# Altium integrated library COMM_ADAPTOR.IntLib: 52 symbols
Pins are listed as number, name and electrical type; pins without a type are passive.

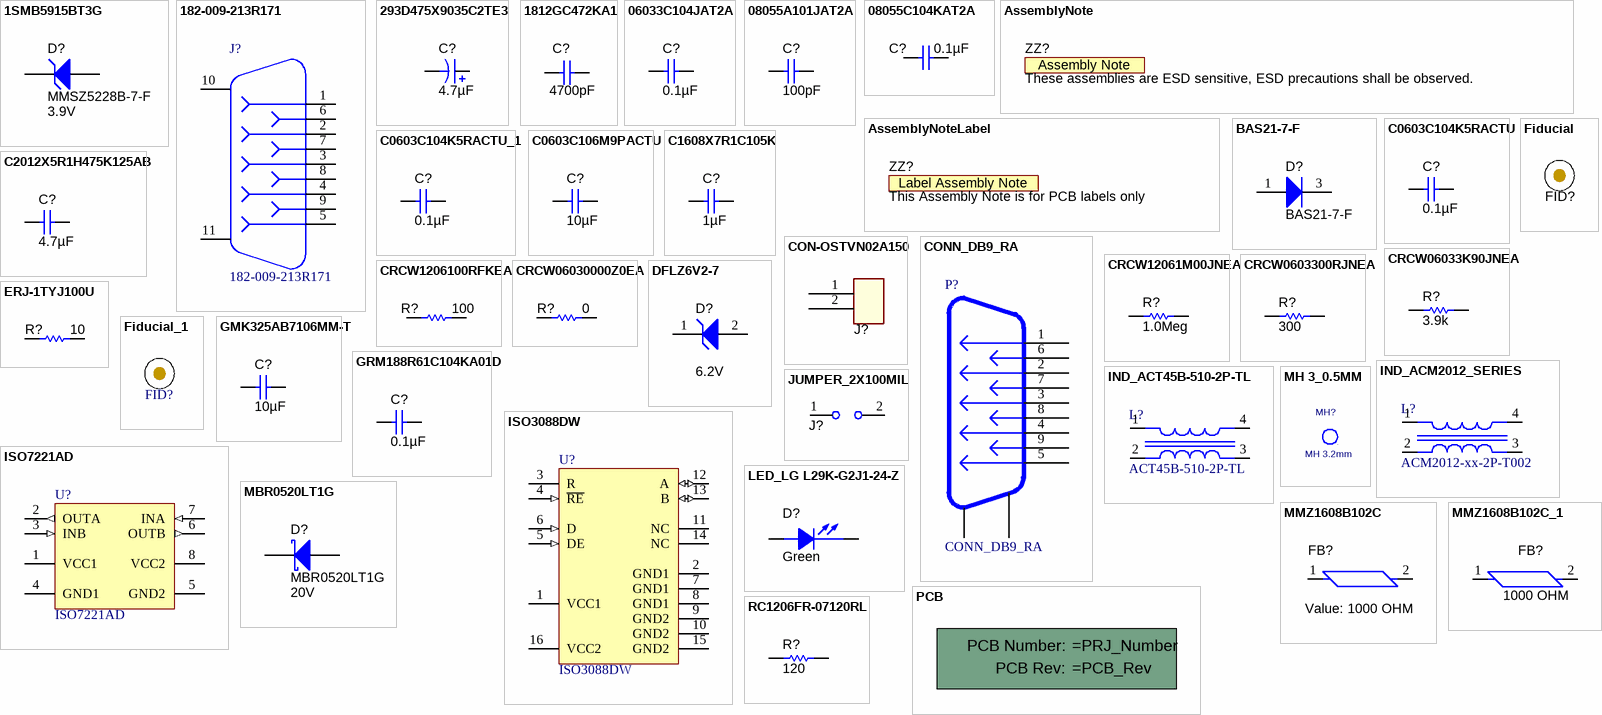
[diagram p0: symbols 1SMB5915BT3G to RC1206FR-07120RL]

## 1SMB5915BT3G
designator D?, comment MMSZ5228B-7-F  value 3.9V
DIODE ZENER 3.9V 500MW SOD123; Manufacturer: Diodes Incorporated; U/M: EA; Power_W: 0.55; Vz_V: 3.9; Value1: 0.55W; RJA_CperW: 226
signal-integrity model Diode
footprint sod-123 (On Semi recommended land pattern)
pins: 1 K, 2 A

## 182-009-213R171
designator J?
CONN DB9 FEMALE R/A SOLDER TH; Manufacturer: NorComp; SymbolCreator: a0412235; CompType: Connector; U/M: EA
footprint NORCOMP_182-009-213R171
pins: 1, 2, 3, 4, 5, 6, 7, 8, 9, 10, 11

## 293D475X9035C2TE3
designator C?  ValueDisplayed: 4.7µF  (hidden comment: 293D475X9035C2TE3)
CAP, TA, 4.7uF, 35V, +/-10%, 1.9 ohm, SMD; Manufacturer: Vishay-Sprague; Polarized: Y; CompType: Capacitor; U/M: EA; Cap_F: 0.0000047; Tolerance_%: 10; Value1: 1.9 ohm; VDC_V: 35; ESR_Ohm: 1.9; IRMS_A: 0.24; TaMin_C: -55; TaMax_C: 125; Cap_Case: C
signal-integrity model Cap
simulation model Cap
footprint 6032-28 (Medium Density IPC based on Vishay Sprague 293D datasheet.)
pins: 1 +, 2 -

## 1812GC472KA1
designator C?  ValueDisplayed: 4700pF  (hidden comment: 1812GC472KA1)
CAP, CERM, 4700pF, 2000V, +/-10%, X7R, 1812; Manufacturer: AVX; Polarized: N; CompType: Capacitor; U/M: EA; Cap_F: 0.0000000047; Tolerance_%: 10; Value1: Unknown; VDC_V: 2000; TaMin_C: -55; TaMax_C: 125; Cap_Case: 1812
signal-integrity model Cap
simulation model Cap
footprint 1812
footprint 1812M
footprint 1812L
footprint 1812_HV
pins: 1, 2

## 06033C104JAT2A
designator C?  ValueDisplayed: 0.1µF  (hidden comment: 06033C104JAT2A)
CAP, CERM, 0.1uF, 25V, +/-5%, X7R, 0603; Manufacturer: AVX; Polarized: N; CompType: Capacitor; U/M: EA; Cap_F: 0.0000001; Tolerance_%: 5; ESR_Ohm: 0.05; Value1: 0.05 ohm; VDC_V: 25; TaMin_C: -55; TaMax_C: 125; Cap_Case: 0603
signal-integrity model Cap
simulation model Cap
footprint 0603
footprint 0603M
footprint 0603L
footprint 0603_HV
pins: 1, 2

## 08055A101JAT2A
designator C?  ValueDisplayed: 100pF  (hidden comment: 08055A101JAT2A)
CAP, CERM, 100pF, 50V, +/-5%, C0G/NP0, 0805; Manufacturer: AVX; Polarized: N; CompType: Capacitor; U/M: EA; Cap_F: 0.0000000001; Tolerance_%: 5; ESR_Ohm: 0.356; Value1: 0.356 ohm; VDC_V: 50; TaMin_C: -55; TaMax_C: 125; Cap_Case: 0805
signal-integrity model Cap
simulation model Cap
footprint 0805_HV
footprint 0805
footprint 0805M
footprint 0805L
pins: 1, 2

## 08055C104KAT2A
designator C?  ValueDisplayed: 0.1µF  (hidden comment: 08055C104KAT2A)
CAP, CERM, 0.1uF, 50V, +/-10%, X7R, 0805; Manufacturer: AVX; Polarized: N; CompType: Capacitor; U/M: EA; Cap_F: 0.0000001; Tolerance_%: 10; ESR_Ohm: 0.024; Value1: 0.024 ohm; VDC_V: 50; TaMin_C: -55; TaMax_C: 125; Cap_Case: 0805
signal-integrity model Cap
simulation model Cap
footprint 0805_HV (0805 with 30mil clearance between pads)
footprint 0805
footprint 0805M
footprint 0805L
pins: 1, 2

## AssemblyNote
designator ZZ?, comment These assemblies are ESD sensitive, ESD precautions shall be observed.  (no BOM)
SymbolCreator: codlsc; CompType: AssemblyNote
footprint AssemblyNote

## AssemblyNoteLabel
designator ZZ?, comment This Assembly Note is for PCB labels only  (no BOM)
SymbolCreator: a0412235
footprint AssemblyNoteLabel

## BAS21-7-F
designator D?
Diode, Switching, 200V, 0.2A, SOT-23; Manufacturer: Diodes Inc.; U/M: EA; Vf_V: 1.25; Value2: 1.25V; Io_A: 0.2; Vr_V: 200; TJmax_C: 150; RJC_CperW: 500
footprint SOT-23 (SOT23, 3-Leads, Body 2.9x1.3mm, Pitch 0.95mm, Lead Span 2.5mm, IPC Medium Density)
footprint SOT-23M
footprint SOT-23L
pins: 1 A, 3 K

## C0603C104K5RACTU
designator C?  ValueDisplayed: 0.1µF
CAP, CERM, 0.1uF, 50V, +/-10%, X7R, 0603; PartNumber: C0603C104K5RACTU; Manufacturer: Kemet; Polarized: N; CompType: Capacitor; U/M: EA; Cap_F: 0.0000001; Tolerance_%: 10; Value1: Unknown; VDC_V: 50; TaMin_C: -55; TaMax_C: 125; Cap_Case: 0603
signal-integrity model Cap
simulation model Cap
footprint 0603 (0603 from SM-752 data)
footprint 0603M
footprint 0603L
footprint 0603_HV
pins: 1, 2

## C0603C104K5RACTU_1
designator C?, comment ValueDisplayed: 0.1µF  (hidden comment: C0603C104K5RACTU)
CAP, CERM, 0.1uF, 50V, +/-10%, X7R, 0603; Manufacturer: Kemet; Polarized: N; CompType: Capacitor; U/M: EA; Cap_F: 0.0000001; Tolerance_%: 10; Value1: Unknown; VDC_V: 50; TaMin_C: -55; TaMax_C: 125; Cap_Case: 0603
signal-integrity model Cap
simulation model Cap
footprint 0603 (0603 from SM-752 data)
footprint 0603M
footprint 0603L
footprint 0603_HV
pins: 1, 2

## C0603C106M9PACTU
designator C?  ValueDisplayed: 10µF  (hidden comment: C0603C106M9PACTU)
CAP, CERM, 10uF, 6.3V, +/-20%, X5R, 0603; Manufacturer: Kemet; Polarized: N; CompType: Capacitor; U/M: EA; Cap_F: 0.00001; Tolerance_%: 20; ESR_Ohm: 0.004; Value1: 0.004 ohm; VDC_V: 6.3; IRMS_A: 8.9; TaMin_C: -55; TaMax_C: 85; Cap_Case: 0603
signal-integrity model Cap
simulation model Cap
footprint 0603
footprint 0603M
footprint 0603L
footprint 0603_HV
pins: 1, 2

## C1608X7R1C105K
designator C?  ValueDisplayed: 1µF  (hidden comment: C1608X7R1C105K)
CAP, CERM, 1uF, 16V, +/-10%, X7R, 0603; Manufacturer: TDK; Polarized: N; CompType: Capacitor; U/M: EA; Cap_F: 0.000001; Tolerance_%: 10; ESR_Ohm: 0.0057; Value1: 0.0057 ohm; VDC_V: 16; TaMin_C: -55; TaMax_C: 125; Cap_Case: 0603
signal-integrity model Cap
simulation model Cap
footprint 0603 (0603 from SM-752 data)
footprint 0603M
footprint 0603L
footprint 0603_HV
pins: 1, 2

## C2012X5R1H475K125AB
designator C?  ValueDisplayed: 4.7µF
CAP, CERM, 4.7uF, 50V, +/-10%, X5R, 0805; PartNumber: C2012X5R1H475K125AB; Manufacturer: TDK; Polarized: N; CompType: Capacitor; U/M: EA; Cap_F: 0.0000047; Tolerance_%: 10; Value1: Unknown; VDC_V: 50; TaMin_C: -55; TaMax_C: 85; Cap_Case: 0805
signal-integrity model Cap
simulation model Cap
footprint 0805_HV (0805 with 30mil clearance between pads)
footprint 0805
footprint 0805M
footprint 0805L
pins: 1, 2

## CON-OSTVN02A150
designator J?  (value not drawn)
CONN TERM BLOCK 2.54MM 2POS PCB; Manufacturer: On Shore Technology Inc; SymbolCreator: x0120606; CompType: Terminal Block
footprint CN2_MTB_P100_PD80_D1.1_S5.54X6.5_STACK
pins: 1, 2

## CONN_DB9_RA
designator P?
Connector, 9-pin D, Right Angle, Male; Manufacturer: AMP; PartNumber: 747250-4; area: 1.021 inch; Value: 747250-4
footprint DB9_RA
pins: 1, 2, 3, 4, 5, 6, 7, 8, 9, 10 MOUNT1, 11 MOUNT2

## CRCW06033K90JNEA
designator R?  value 3.9k
RES, 3.9k ohm, 5%, 0.1W, 0603; PartNumber: CRCW06033K90JNEA; Manufacturer: Vishay-Dale; CompType: Resistor; Res_ohm: 3900; Value_Code: 3k90; Tolerance_%: 5; Power_W: 0.1; VDC_V: 75; TempCo: 200 ppm/C; EIA_Code: E24; U/M: EA
signal-integrity model Resistor
simulation model Resistor
footprint 0603 (0603 from SM-752 data)
footprint 0603M
footprint 0603L
footprint 0603_HV
footprint 0603
footprint 0603_HV
footprint 0603L
footprint 0603M
simulation model Resistor
signal-integrity model Resistor
pins: 1, 2

## CRCW12061M00JNEA
designator R?  value 1.0Meg  (hidden comment: CRCW12061M00JNEA)
RES, 1.0Meg ohm, 5%, 0.25W, 1206; Manufacturer: Vishay-Dale; CompType: Resistor; Res_ohm: 1000000; Value_Code: 1M00; Tolerance_%: 5; Power_W: 0.25; VDC_V: 200; TempCo: 200 ppm/C; EIA_Code: E24; U/M: EA
signal-integrity model Resistor
simulation model Resistor
footprint 1206 (1206 from SM-752 data)
footprint 1206M
footprint 1206L
pins: 1, 2

## CRCW0603300RJNEA
designator R?  value 300  (hidden comment: CRCW0603300RJNEA)
RES, 300 ohm, 5%, 0.1W, 0603; Manufacturer: Vishay-Dale; CompType: Resistor; Value_Code: 300R; Tolerance_%: 5; Power_W: 0.1; VDC_V: 75; TempCo: 200 ppm/C; EIA_Code: E24; U/M: EA
signal-integrity model Resistor
simulation model Resistor
footprint 0603 (0603 from SM-752 data)
footprint 0603M
footprint 0603L
footprint 0603_HV
footprint 0603
footprint 0603_HV
footprint 0603L
footprint 0603M
simulation model Resistor
signal-integrity model Resistor
pins: 1, 2

## CRCW1206100RFKEA
designator R?  value 100  (hidden comment: CRCW1206100RFKEA)
RES, 100 ohm, 1%, 0.25W, 1206; Manufacturer: Vishay-Dale; CompType: Resistor; Value_Code: 100R; Tolerance_%: 1; Power_W: 0.25; VDC_V: 200; TempCo: 100 ppm/C; EIA_Code: E96; U/M: EA
signal-integrity model Resistor
simulation model Resistor
footprint 1206
footprint 1206M
footprint 1206L
pins: 1, 2

## CRCW06030000Z0EA
designator R?  value 0  (hidden comment: CRCW06030000Z0EA)
RES, 0 ohm, 5%, 0.1W, 0603; Manufacturer: Vishay-Dale; CompType: Resistor; Value_Code: 0000; Tolerance_%: 5; Power_W: 0.1; VDC_V: 75; TempCo: 200 ppm/C; EIA_Code: E24; U/M: EA
signal-integrity model Resistor
simulation model Resistor
footprint 0603
footprint 0603M
footprint 0603L
footprint 0603_HV
pins: 1, 2

## DFLZ6V2-7
designator D?  value 6.2V
Diode, Zener, 6.2V, 1W, PowerDI123; PartNumber: DFLZ6V2-7; Manufacturer: Diodes Inc.; U/M: EA; Power_W: 1; Vz_V: 6.2; RJA_CperW: 110
signal-integrity model Diode
footprint powerDI123 (Diodes Inc recommended land pattern, document number DS30628 Rev. 6-2)
pins: 1 K, 2 A

## ERJ-1TYJ100U
designator R?  value 10  (hidden comment: ERJ-1TYJ100U)
RES, 10 ohm, 5%, 1W, 2512; Manufacturer: Panasonic; CompType: Resistor; Value_Code: 10R0; Tolerance_%: 5; Power_W: 1; VDC_V: 200; TempCo: 200 ppm/C; EIA_Code: E24; U/M: EA
signal-integrity model Resistor
simulation model Resistor
footprint 2512M
footprint 2512L
footprint 2512
pins: 1, 2

## Fiducial
designator FID?  (value not drawn)
Fiducial mark.  There is nothing to buy or mount.; SymbolCreator: codlsc
footprint Fiducial10-30
footprint Fiducial10-20
footprint Fiducial15-30
footprint Fiducial20-40
footprint Fiducial6.4-20
footprint Fiducial10-30_TopLayerKeepOutOnly
footprint Fiducial6.4-20_TopLayerKeepOutOnly
footprint Fiducial10-20_TopLayerKeepOutOnly
footprint Fiducial15-30_TopLayerKeepOutOnly
footprint Fiducial20-40_TopLayerKeepOutOnly

## Fiducial_1
designator FID?, comment Fiducial  (value not drawn)
Fiducial mark.  There is nothing to buy or mount.; SymbolCreator: codlsc
footprint Fiducial10-30
footprint Fiducial10-20
footprint Fiducial15-30
footprint Fiducial20-40
footprint Fiducial6.4-20
footprint Fiducial10-30_Panel

## GMK325AB7106MM-T
designator C?  ValueDisplayed: 10µF
CAP, CERM, 10uF, 35V, +/-20%, X7R, 1210; PartNumber: GMK325AB7106MM-T; Manufacturer: Taiyo Yuden; Polarized: N; CompType: Capacitor; U/M: EA; Cap_F: 0.00001; Tolerance_%: 20; Value1: Unknown; VDC_V: 35; TaMin_C: -55; TaMax_C: 125; Cap_Case: 1210
signal-integrity model Cap
simulation model Cap
footprint 1210 (1210 from SM-752 data)
footprint 1210M
footprint 1210L
pins: 1, 2

## GRM188R61C104KA01D
designator C?  ValueDisplayed: 0.1µF  (hidden comment: GRM188R61C104KA01D)
CAP, CERM, 0.1uF, 16V, +/-10%, X5R, 0603; Manufacturer: MuRata; Polarized: N; CompType: Capacitor; U/M: EA; Cap_F: 0.0000001; Tolerance_%: 10; Value1: Unknown; VDC_V: 16; TaMin_C: -55; TaMax_C: 85; Cap_Case: 0603
signal-integrity model Cap
simulation model Cap
footprint 0603
footprint 0603M
footprint 0603L
footprint 0603_HV
pins: 1, 2

## IND_ACM2012_SERIES
designator L?, comment ACM2012-xx-2P-T002
Inductor, Common Mode Filter SMD; Manufacturer: TDK; Area: 8.13 mm; Value: xx uH
footprint IND_0805-4P
pins: 1, 2, 3, 4

## IND_ACT45B-510-2P-TL
designator L?, comment ACT45B-510-2P-TL
Inductor, Common Mode Fiolter; Manufacturer: TDK; Area: 63.64 mm
footprint IND_3.2X4.5MM-4P
pins: 1, 2, 3, 4

## ISO3088DW
designator U?
Isolated RS-485 Transceiver, 20 Mbps, 5 V, Half Duplex, -40 to 85 degC, 16-pin SOIC (DW); Manufacturer: Texas Instruments; Alternate Manufacturer: None; Alternate PartNumber: Equivalent; Eco-Plan: TBD; # of TX/RX: 1 TX / 1 RX; Drivers Per Package: 1; Isolated: Yes; Number of Nodes: 256; Signaling Rate(Mbps): 20; Common Mode Range: -7 to 12; ESD(kV): 16; Fault Protection(V): -9 to 14; Fail Safe: Idle, Open, Short; ICC(Max)(mA): 15; Supply Voltage(s)(V): 5; Rating: Catalog
footprint DW0016A_N (SOIC, 16-Leads, Body 10.3x7.5mm, Pitch 1.27mm, IPC Medium Density)
footprint DW0016A_L (SOIC, 16-Leads, Body 10.3x7.5mm, Pitch 1.27mm, IPC High Density)
footprint DW0016A_M (SOIC, 16-Leads, Body 10.3x7.5mm, Pitch 1.27mm, IPC Low Density)
pins: 1 VCC1 (power), 2 GND1 (power), 3 R (hiz), 4 ~{RE} (in), 5 DE (in), 6 D (in), 7 GND1 (power), 8 GND1 (power), 9 GND2 (power), 10 GND2 (power), 11 NC, 12 A (io), 13 B (io), 14 NC, 15 GND2 (power), 16 VCC2 (power)

## ISO7221AD
designator U?
1 Mbps Dual Channels, 1 / 1, Digital Isolator, 3.3 V / 5 V, -40 to +125 degC, 8-pin SOIC (D), Green (RoHS & no Sb/Br); Manufacturer: Texas Instruments; Alternate Manufacturer: None; Alternate PartNumber: Equivalent; Datarate(Mbps): 1; Input Noise Filter: Yes; Insulation Rating(VRMS): 2500; Prop Delay(Max)(ns): 475; Rating: Catalog; Supply Voltage(s)(V): 3.3, 5; TTL/CMOS Input Threshold: TTL
footprint D0008A_N (SOIC, 8-Leads, Body 5x4mm, Pitch 1.27mm, IPC Medium Density)
footprint D0008A_L (SOIC, 8-Leads, Body 5x4mm, Pitch 1.27mm, IPC High Density)
footprint D0008A_M (SOIC, 8-Leads, Body 5x4mm, Pitch 1.27mm, IPC Low Density)
pins: 1 VCC1 (power), 2 OUTA (out), 3 INB (in), 4 GND1 (power), 5 GND2 (power), 6 OUTB (out), 7 INA (in), 8 VCC2 (power)

## JUMPER_2X100MIL
designator J?
Header, Male 2-pin, 100mil spacing,; Manufacturer: Sullins; PartNumber: PEC02SAAN; area: 20000; Value: PEC02SAAN
footprint HDR100_1X2
pins: 1, 2

## LED_LG L29K-G2J1-24-Z
designator D?  value Green
LED SmartLED Green 570NM; PartNumber: LG L29K-G2J1-24-Z; Manufacturer: OSRAM; SymbolCreator: x0120606
footprint LED0603AA
pins: 1 C, 2 A

## MBR0520LT1G
designator D?  value 20V
Diode, Schottky, 20V, 0.5A, SOD-123; Manufacturer: ON Semiconductor; U/M: EA; Vf_V: 0.385; Value2: 0.385V; Io_A: 0.5; Vr_V: 20; TJmax_C: 125; RJC_CperW: 150
signal-integrity model Diode
simulation model mbr0520lt1
footprint SOD-123 (On Semi recommended land pattern)
pins: 1 K, 2 A

## MH 3_0.5MM
designator MH?, comment MH 3.2mm
Mountin hole, NPTH Drill 3.2mm
footprint MH3.2_H5_W6_KO8_STARHEAD
pins: 1

## MMZ1608B102C
designator FB?  value 1000 OHM
FERRITE CHIP 1000 OHM 300MA 0603; PartNumber: MMZ1608B102C; Manufacturer: TDK Corporation; CompType: Ferrite Bead
footprint FB0603
pins: 1, 2

## MMZ1608B102C_1
designator FB?, comment 1000 OHM
FERRITE CHIP 1000 OHM 300MA 0603; PartNumber: MMZ1608B102C; Manufacturer: TDK Corporation; CompType: Ferrite Bead
footprint 0603 (0603 from SM-752 data)
pins: 1, 2

## PCB
designator !PCB?, comment Printed Circuit Board  (value not drawn)  (mechanical)
Manufacturer: Any; SymbolCreator: a0412235; CompType: PCB
1 alternate drawing of the same symbol

## RC1206FR-07120RL
designator R?  value 120  (hidden comment: RC1206FR-07120RL)
RES, 120 ohm, 1%, 0.25W, 1206; Manufacturer: Yageo America; CompType: Resistor; Value_Code: 120R; Tolerance_%: 1; Power_W: 0.25; VDC_V: 200; TempCo: 100 ppm/C; U/M: EA
signal-integrity model Resistor
simulation model Resistor
footprint 1206
footprint 1206M
footprint 1206L
pins: 1, 2

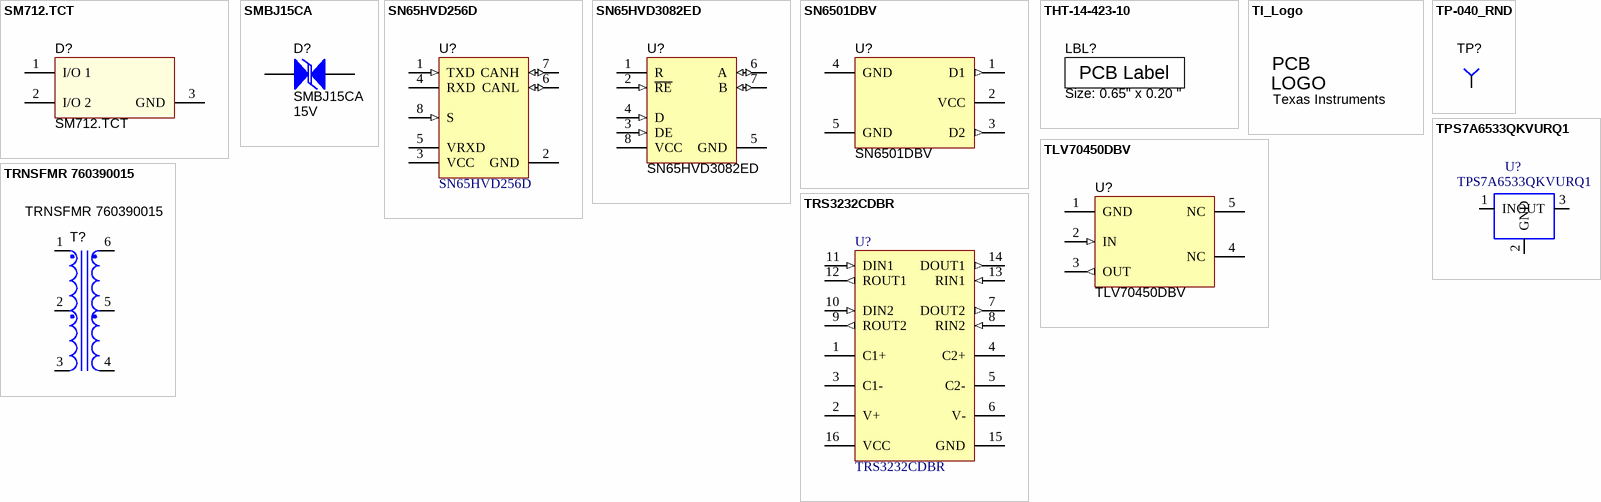
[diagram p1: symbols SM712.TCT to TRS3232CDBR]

## SM712.TCT
designator D?
IC TVS ASYMM RS-485V 7/12V SOT23; Manufacturer: Semtech; Voltage - Reverse Standoff (Typ): 12V; Voltage - Breakdown: 13.3V; Power_W: 400W; Polarization: 2 Channel Array - Bidirectional
footprint SM712.TCT (Footprint not found)
pins: 1 I/O 1, 2 I/O 2, 3 GND

## SMBJ15CA
designator D?  value 15V
Diode, TVS, Bi, 15V, 600W, SMB; Manufacturer: Littelfuse; U/M: EA; Power_W: 600; Vr_V: 15; RJA_CperW: 100
footprint SMB
pins: 1, 2

## SN65HVD256D
designator U?
CAN Transceiver with Fast Loop Times for Highly Loaded Networks, 85 mA, 5 V, -40 to 125 degC, 8-pin SOIC (D), Green (RoHS & no Sb/Br); Manufacturer: Texas Instruments; Alternate Manufacturer: None; Alternate PartNumber: Equivalent; Drivers Per Package: 1; Bus Fault Voltage(V): -27 to 40; ICC(Max)(mA): 85; Supply Voltage(s)(V): 5; Rating: Catalog
footprint D0008A_N (SOIC, 8-Leads, Body 4.9x3.9mm, Pitch 1.27mm, IPC Medium Density)
footprint D0008A_L (SOIC, 8-Leads, Body 4.9x3.9mm, Pitch 1.27mm, IPC High Density)
footprint D0008A_M (SOIC, 8-Leads, Body 4.9x3.9mm, Pitch 1.27mm, IPC Low Density)
pins: 1 TXD (in) "CAN transmit data input (LOW for dominant and HIGH for recessive bus states)", 2 GND (power) "Ground connection", 3 VCC (power) "Transceiver 5V supply voltage", 4 RXD (hiz) "CAN receive data output (LOW for dominant and HIGH for recessive bus states)", 5 VRXD (power) "RXD output supply voltage", 6 CANL (io) "Low level CAN bus line", 7 CANH (io) "High level CAN bus line", 8 S (in) "S (Silent Mode) select pin (active high)"

## SN65HVD3082ED
designator U?
IC, RS485 TRANSCEIVER LP, 8-SOIC; Manufacturer: TEXAS INSTRUMENTS; CompType: LOW-POWER RS-485 TRANSCEIVER; SymbolCreator: x0199378
footprint D0008A_N (SOIC, 8-Leads, Body 4.9x3.9mm, Pitch 1.27mm, IPC Medium Density)
pins: 1 R (hiz), 2 ~{RE} (in), 3 DE (in), 4 D (in), 5 GND (power), 6 A (io), 7 B (io), 8 VCC (power)

## SN6501DBV
designator U?
Transformer Driver for Isolated Power Supplies, DBV0005A; Alternate Manufacturer: None; Manufacturer: Texas Instruments; SymbolCreator: a0411947; CompType: IC; U/M: EA
footprint DBV0005A_N (SOT23, 5-Leads, Body 2.9x1.6mm, Pitch 0.95mm, Lead Span 2.8mm, IPC Medium Density)
footprint DBV0005A_M
footprint DBV0005A_L
pins: 1 D1 (out), 2 VCC (power), 3 D2 (out), 4 GND (power), 5 GND (power)

## THT-14-423-10
designator LBL?, comment Size: 0.65" x 0.20 "
Thermal Transfer Printable Labels, 0.650" W x 0.200" H - 10,000 per roll; Manufacturer: Brady; PartNumber: THT-14-423-10; SymbolCreator: a0412235; CompType: Label
footprint Label_650x200

## TI_Logo
designator Logo?, comment Texas Instruments  (no BOM)
Texas Instrument Corporate Signature; SymbolCreator: codlsc
footprint TI_Stacked_SolderMask_Medium
footprint TI_Stacked_SolderMask_Small
footprint TI_Stacked_Overlay_Medium
footprint TI_Stacked_Overlay_Small
footprint TI_Horizontal_SolderMask_Medium
footprint TI_Horizontal_SolderMask_Small
footprint TI_Horizontal_Overlay_Medium
footprint TI_Horizontal_Overlay_Small
footprint TI_Symbol_SolderMask_Small
footprint TI_Symbol_Overlay_Medium
footprint TI_Symbol_Overlay_Small
footprint TI_Symbol_SolderMask_Medium

## TLV70450DBV
designator U?
Regulator, LDO, 5V, 0.15A, SOT23-5; Alternate Manufacturer: None; Manufacturer: Texas Instruments; SymbolCreator: x0120606; CompType: IC
footprint DBV0005A_N (SOT23, 5-Leads, Body 2.9x1.6mm, Pitch 0.95mm, Lead Span 2.8mm, IPC Medium Density)
footprint DBV0005A_M
footprint DBV0005A_L
pins: 1 GND (power), 2 IN (in), 3 OUT (out), 4 NC (power), 5 NC (power)
1 alternate drawing of the same symbol

## TP-040_RND
designator TP?
Test Point, O.040 Hole; Manufacturer: STD; Value: STD
footprint TP-040_RND
pins: 1

## TPS7A6533QKVURQ1
designator U?
IC, 300-mA 40-V LOW-DROPOUT REGULATOR WITH 25-uA QUIESCENT CURRENT; Manufacturer: TI; Alternate Manufacturer: None; Area: 136210
footprint KVU_1
pins: 1 IN, 2 GND, 3 OUT

## TRNSFMR 760390015
designator T?
Transformer 475uH SMD; Manufacturer: Wurth Electronics Midcom
footprint 760390015
pins: 1, 2, 3, 4, 5, 6

## TRS3232CDBR
designator U?
3-V to 5.5-V Multichannel RS-232 Line Driver / Receiver with ±15-kV ESD Protection, 0 to 70 degC, 16-Pin SSOP (DB),  Green (RoHS & no Sb/Br); Manufacturer: Texas Instruments; Alternate Manufacturer: None; Alternate PartNumber: Equivalent; Drivers Per Package: 2; Supply Voltage(s)(V): 3.3 or 5.0; ESD HBM(kV): +/-15; ICC(Max)(mA): 1; Single Supply: TRUE
footprint DB0016A_N (SOP, 16-Leads, Body 6.2x5.3mm, Pitch 0.65mm, IPC Medium Density)
footprint DB0016A_L (SOP, 16-Leads, Body 6.2x5.3mm, Pitch 0.65mm, IPC High Density)
footprint DB0016A_M (SOP, 16-Leads, Body 6.2x5.3mm, Pitch 0.65mm, IPC Low Density)
pins: 1 C1+, 2 V+ (power), 3 C1-, 4 C2+, 5 C2-, 6 V- (power), 7 DOUT2 (out), 8 RIN2 (in), 9 ROUT2 (out), 10 DIN2 (in), 11 DIN1 (in), 12 ROUT1 (out), 13 RIN1 (in), 14 DOUT1 (out), 15 GND (power), 16 VCC (power)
